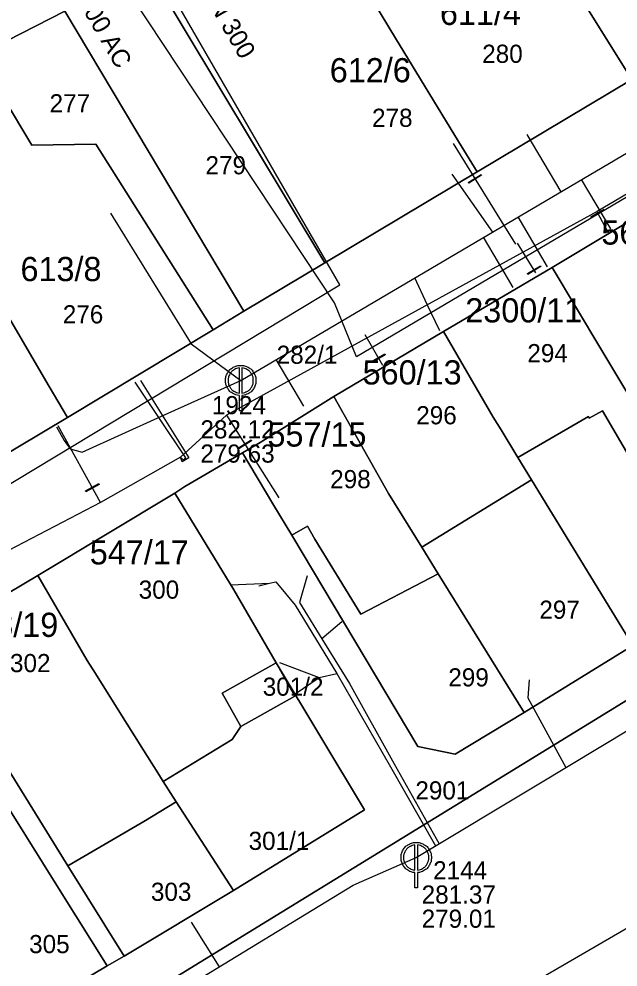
# Model space of a CAD drawing. Extents: x -571312 to -571060, y -1087128 to -1086933.
# Drawn here: x -571203.4 to -571153.9, y -1087085.5 to -1087007.2 of the extents above; entities that cross this region are included whole.
import ezdxf

# ---------------------------------------------------------------- set-up
doc = ezdxf.new("R2010")
doc.units = 0
for name, color, linetype in [('Adresní místo-text', 7, 'Continuous'), ('Armatura vodovodní', 7, 'Continuous'), ('Default', 7, 'Continuous'), ('Elektro NN - vedení', 7, 'Continuous'), ('Kanalizační přípojka', 7, 'Continuous'), ('Kanalizační stoka', 7, 'Continuous'), ('Kanalizační šachta', 7, 'Continuous'), ('Parcela-polygon', 7, 'Continuous'), ('Parcela-text', 7, 'Continuous'), ('Popis šachty', 7, 'Continuous'), ('Vodovodní přípojka', 7, 'Continuous'), ('Vodovodní řad', 7, 'Continuous'), ('Řad vodovodní popis', 7, 'Continuous')]:
    doc.layers.add(name, color=color, linetype=linetype)

msp = doc.modelspace()

# ---------------------------------------------------------------- linework, layer by layer
at = {"layer": 'Armatura vodovodní'}
for points in [[(-571165.211, -1087020.113), (-571166.272, -1087020.773), (-571166.314, -1087020.707), (-571165.252, -1087020.047), (-571165.211, -1087020.113)], [(-571155.048, -1087022.996), (-571156.133, -1087023.617), (-571156.172, -1087023.55), (-571155.087, -1087022.928), (-571155.048, -1087022.996)], [(-571160.313, -1087027.663), (-571161.379, -1087028.317), (-571161.42, -1087028.25), (-571160.354, -1087027.596), (-571160.313, -1087027.663)], [(-571173.176, -1087034.954), (-571174.256, -1087035.583), (-571174.295, -1087035.516), (-571173.215, -1087034.887), (-571173.176, -1087034.954)], [(-571184.208, -1087042.055), (-571185.264, -1087042.723), (-571185.306, -1087042.656), (-571184.25, -1087041.989), (-571184.208, -1087042.055)], [(-571196.804, -1087045.663), (-571197.895, -1087046.273), (-571197.933, -1087046.205), (-571196.842, -1087045.595), (-571196.804, -1087045.663)]]:
    msp.add_lwpolyline(points, dxfattribs=at)
at = {"layer": 'Default'}
for points in [[(-571185.213, -1087038.328), (-571185.471, -1087038.31), (-571185.733, -1087038.164), (-571186.03, -1087038), (-571186.195, -1087037.703), (-571186.36, -1087037.405), (-571186.36, -1087037.08), (-571186.36, -1087036.753), (-571186.192, -1087036.453), (-571186.023, -1087036.152), (-571185.725, -1087035.991), (-571185.427, -1087035.83), (-571185.11, -1087035.83), (-571184.795, -1087035.83), (-571184.496, -1087035.991), (-571184.197, -1087036.152), (-571184.028, -1087036.453), (-571183.86, -1087036.753), (-571183.86, -1087037.08), (-571183.86, -1087037.405), (-571184.025, -1087037.703), (-571184.19, -1087038), (-571184.487, -1087038.164), (-571184.749, -1087038.31), (-571185.007, -1087038.328)], [(-571185.213, -1087036.042), (-571185.41, -1087036.059), (-571185.625, -1087036.174), (-571185.874, -1087036.309), (-571186.013, -1087036.559), (-571186.152, -1087036.809), (-571186.152, -1087037.08), (-571186.152, -1087037.351), (-571186.016, -1087037.598), (-571185.879, -1087037.844), (-571185.63, -1087037.981), (-571185.418, -1087038.101), (-571185.213, -1087038.115)], [(-571185.007, -1087038.115), (-571184.802, -1087038.101), (-571184.588, -1087037.981), (-571184.341, -1087037.844), (-571184.204, -1087037.598), (-571184.068, -1087037.351), (-571184.068, -1087037.08), (-571184.068, -1087036.809), (-571184.208, -1087036.559), (-571184.348, -1087036.309), (-571184.597, -1087036.174), (-571184.81, -1087036.059), (-571185.007, -1087036.042)], [(-571170.713, -1087077.748), (-571170.971, -1087077.73), (-571171.233, -1087077.584), (-571171.53, -1087077.42), (-571171.695, -1087077.123), (-571171.86, -1087076.825), (-571171.86, -1087076.5), (-571171.86, -1087076.173), (-571171.692, -1087075.873), (-571171.523, -1087075.572), (-571171.225, -1087075.411), (-571170.927, -1087075.25), (-571170.61, -1087075.25), (-571170.295, -1087075.25), (-571169.996, -1087075.411), (-571169.697, -1087075.572), (-571169.528, -1087075.873), (-571169.36, -1087076.173), (-571169.36, -1087076.5), (-571169.36, -1087076.825), (-571169.525, -1087077.123), (-571169.69, -1087077.42), (-571169.987, -1087077.584), (-571170.249, -1087077.73), (-571170.507, -1087077.748)], [(-571170.713, -1087075.462), (-571170.91, -1087075.479), (-571171.125, -1087075.594), (-571171.374, -1087075.729), (-571171.513, -1087075.979), (-571171.652, -1087076.229), (-571171.652, -1087076.5), (-571171.652, -1087076.771), (-571171.516, -1087077.018), (-571171.379, -1087077.264), (-571171.13, -1087077.401), (-571170.918, -1087077.521), (-571170.713, -1087077.535)], [(-571170.507, -1087077.535), (-571170.302, -1087077.521), (-571170.088, -1087077.401), (-571169.841, -1087077.264), (-571169.704, -1087077.018), (-571169.568, -1087076.771), (-571169.568, -1087076.5), (-571169.568, -1087076.229), (-571169.708, -1087075.979), (-571169.848, -1087075.729), (-571170.097, -1087075.594), (-571170.31, -1087075.479), (-571170.507, -1087075.462)]]:
    msp.add_open_spline(points, degree=3, dxfattribs=at)
at = {"layer": 'Elektro NN - vedení'}
msp.add_lwpolyline([(-571071.926, -1087014.396), (-571073.5, -1087015.707), (-571083.992, -1087003.116), (-571092.911, -1086996.034), (-571095.272, -1086994.46), (-571113.896, -1086998.657), (-571175.538, -1087035.118), (-571177.374, -1087030.659), (-571213.311, -1086976.361), (-571216.983, -1086969.541), (-571228.263, -1086944.884), (-571229.263, -1086941.883)], dxfattribs=at)
at = {"layer": 'Kanalizační přípojka'}
for points in [[(-571161.465, -1087016.747), (-571160.068, -1087019.116), (-571158.671, -1087021.484)], [(-571167.678, -1087020.016), (-571165.996, -1087022.414), (-571164.314, -1087024.813)], [(-571154.546, -1087024.54), (-571155.747, -1087022.504), (-571156.948, -1087020.468)], [(-571195.864, -1087023.248), (-571192.527, -1087028.649), (-571189.19, -1087034.05), (-571185.11, -1087037.08)], [(-571159.76, -1087027.688), (-571162.193, -1087023.562)], [(-571162.589, -1087029.399), (-571163.815, -1087027.32), (-571165.041, -1087025.242)], [(-571168.666, -1087032.982), (-571169.698, -1087030.789), (-571170.729, -1087028.597)], [(-571179.904, -1087039.214), (-571182.182, -1087035.353)], [(-571200.32, -1087040.9), (-571199.69, -1087042.04), (-571199.2, -1087042.73), (-571198.22, -1087042.99), (-571191.665, -1087040.035), (-571185.11, -1087037.08)], [(-571179.61, -1087053.22), (-571180.251, -1087055.413), (-571178.191, -1087058.772), (-571176.13, -1087062.13), (-571172.424, -1087068.745), (-571168.717, -1087075.359)], [(-571185.918, -1087053.96), (-571182.733, -1087053.834)], [(-571183.62, -1087054.04), (-571182.73, -1087053.83), (-571182.2, -1087053.71), (-571180.617, -1087055.636), (-571177.161, -1087061.302), (-571172.74, -1087068.996), (-571169.02, -1087075.542)], [(-571176.744, -1087057.029), (-571178.403, -1087058.424)], [(-571181.91, -1087060.396), (-571178.635, -1087061.611)], [(-571180.61, -1087062.978), (-571178.635, -1087061.611), (-571177.161, -1087061.302)], [(-571161.29, -1087061.81), (-571161.39, -1087063.31), (-571158.241, -1087069.047)], [(-571189.19, -1087081.84), (-571186.894, -1087085.536)]]:
    msp.add_lwpolyline(points, dxfattribs=at)
at = {"layer": 'Kanalizační stoka'}
for points in [[(-571185.11, -1087037.08), (-571141.1, -1087011.12)], [(-571170.61, -1087076.5), (-571160.495, -1087070.405), (-571150.38, -1087064.31)], [(-571228.76, -1087111.04), (-571202.29, -1087094.915), (-571175.82, -1087078.79), (-571170.61, -1087076.5)]]:
    msp.add_lwpolyline(points, dxfattribs=at)
at = {"layer": 'Kanalizační šachta'}
for points in [[(-571185.213, -1087038.115), (-571185.213, -1087036.042)], [(-571185.007, -1087036.042), (-571185.007, -1087038.115)], [(-571185.007, -1087038.328), (-571185.007, -1087039.58), (-571185.213, -1087039.58), (-571185.213, -1087038.328)], [(-571170.713, -1087077.535), (-571170.713, -1087075.462)], [(-571170.507, -1087075.462), (-571170.507, -1087077.535)], [(-571170.507, -1087077.748), (-571170.507, -1087079), (-571170.713, -1087079), (-571170.713, -1087077.748)]]:
    msp.add_lwpolyline(points, dxfattribs=at)
at = {"layer": 'Parcela-polygon'}
for points in [[(-571144.15, -1087007.02), (-571155.86, -1086984.54), (-571166.67, -1086989.97), (-571152.8, -1087012.2)], [(-571208.98, -1086985.45), (-571218.36, -1086988.9), (-571217.04, -1086992.42), (-571226.94, -1086996.1), (-571217.97, -1087015.93), (-571206.82, -1087010.23), (-571199.65, -1087006.57), (-571207.52, -1086988.77)], [(-571179.74, -1086996.54), (-571179.19, -1086997.45), (-571175.25, -1087003.94), (-571172.31, -1087008.78), (-571167.11, -1087017.33), (-571165.57, -1087019.85), (-571152.8, -1087012.2), (-571166.67, -1086989.97)], [(-571179.19, -1086997.45), (-571179.74, -1086996.54), (-571192.72, -1087003.08), (-571178.15, -1087027.35), (-571165.57, -1087019.85), (-571167.11, -1087017.33), (-571172.31, -1087008.78), (-571175.25, -1087003.94)], [(-571178.15, -1087027.35), (-571192.72, -1087003.08), (-571199.65, -1087006.57), (-571184.85, -1087031.35)], [(-571184.85, -1087031.35), (-571199.65, -1087006.57), (-571206.82, -1087010.23), (-571202.38, -1087017.63), (-571197.08, -1087017.54), (-571187.38, -1087032.88)], [(-571197.08, -1087017.54), (-571202.38, -1087017.63), (-571206.82, -1087010.23), (-571217.97, -1087015.93), (-571215.05, -1087019.09), (-571210.21, -1087024.35), (-571206.07, -1087028.84), (-571200.94, -1087037.57), (-571199.42, -1087040.15), (-571187.38, -1087032.88)], [(-571210.21, -1087024.35), (-571215.05, -1087019.09), (-571217.97, -1087015.93), (-571222.72, -1087018.32), (-571218.79, -1087022.67), (-571223.54, -1087027.82), (-571216.62, -1087040.62), (-571216.21, -1087040.39), (-571212.67, -1087046.57), (-571212.04, -1087047.66), (-571199.42, -1087040.15), (-571200.94, -1087037.57), (-571206.07, -1087028.84)], [(-571150.57, -1087022.45), (-571159.39, -1087027.73), (-571155.35, -1087034.47), (-571153.13, -1087038.18), (-571151.82, -1087040.36), (-571143.27, -1087035.13), (-571144.87, -1087032.36), (-571146.38, -1087029.72), (-571146.72, -1087029.14)], [(-571151.82, -1087040.36), (-571153.13, -1087038.18), (-571155.35, -1087034.47), (-571159.39, -1087027.73), (-571168.35, -1087033.04), (-571164.25, -1087040.1), (-571163.6, -1087041.16), (-571162.21, -1087043.44), (-571156.38, -1087040.06), (-571156.31, -1087040.18), (-571155.22, -1087039.59), (-571151.14, -1087046.55), (-571148.91, -1087045.23)], [(-571164.25, -1087040.1), (-571168.35, -1087033.04), (-571177.42, -1087038.4), (-571172.91, -1087046.42), (-571170.16, -1087050.86), (-571161.09, -1087045.28), (-571162.21, -1087043.44), (-571163.6, -1087041.16)], [(-571177.42, -1087038.4), (-571183.51, -1087042.2), (-571184.97, -1087043.06), (-571182.46, -1087047.26), (-571180.9, -1087049.87), (-571179.59, -1087049.13), (-571178.99, -1087050.2), (-571175.19, -1087056.39), (-571168.8, -1087053.05), (-571170.16, -1087050.86), (-571172.91, -1087046.42)], [(-571148.91, -1087045.23), (-571151.14, -1087046.55), (-571155.22, -1087039.59), (-571156.31, -1087040.18), (-571156.38, -1087040.06), (-571162.21, -1087043.44), (-571161.09, -1087045.28), (-571152.72, -1087058.97), (-571143.89, -1087053.63)], [(-571161.09, -1087045.28), (-571170.16, -1087050.86), (-571168.8, -1087053.05), (-571161.7, -1087064.52), (-571152.72, -1087058.97)], [(-571201.86, -1087053.18), (-571197.8, -1087060.21), (-571197.12, -1087061.3), (-571195.24, -1087064.3), (-571193.15, -1087067.62), (-571191.96, -1087069.51), (-571191.52, -1087070.21), (-571185.82, -1087066.75), (-571185.11, -1087065.67), (-571186.65, -1087062.93), (-571182.17, -1087060.4), (-571185.69, -1087054.37), (-571190.56, -1087046.39)], [(-571161.7, -1087064.52), (-571168.8, -1087053.05), (-571175.19, -1087056.39), (-571178.99, -1087050.2), (-571179.59, -1087049.13), (-571180.9, -1087049.87), (-571170.47, -1087067.33), (-571167.4, -1087067.96)], [(-571210.82, -1087058.52), (-571206.5, -1087065.72), (-571199.38, -1087077.18), (-571193.1, -1087073.51), (-571190.45, -1087071.91), (-571191.52, -1087070.21), (-571191.96, -1087069.51), (-571193.15, -1087067.62), (-571195.24, -1087064.3), (-571197.12, -1087061.3), (-571197.8, -1087060.21), (-571201.86, -1087053.18)], [(-571219.73, -1087063.8), (-571215.85, -1087070.21), (-571214.37, -1087072.67), (-571213.37, -1087074.33), (-571210.64, -1087078.7), (-571208.46, -1087077.42), (-571209.1, -1087076.39), (-571205.73, -1087074.32), (-571206.54, -1087072.99), (-571204.26, -1087072.46), (-571200.02, -1087079.25), (-571196.13, -1087085.46), (-571194.74, -1087084.64), (-571199.38, -1087077.18), (-571206.5, -1087065.72), (-571210.82, -1087058.52)], [(-571182.17, -1087060.4), (-571180.64, -1087063.16), (-571185.11, -1087065.67), (-571185.82, -1087066.75), (-571191.52, -1087070.21), (-571190.45, -1087071.91), (-571185.7, -1087079.22), (-571174.89, -1087072.57)], [(-571182.17, -1087060.4), (-571186.65, -1087062.93), (-571185.11, -1087065.67), (-571180.64, -1087063.16)], [(-571199.38, -1087077.18), (-571194.74, -1087084.64), (-571185.7, -1087079.22), (-571190.45, -1087071.91), (-571193.1, -1087073.51)], [(-571205.73, -1087074.32), (-571209.1, -1087076.39), (-571208.46, -1087077.42), (-571210.64, -1087078.7), (-571210.13, -1087079.52), (-571203.69, -1087089.94), (-571196.13, -1087085.46), (-571200.02, -1087079.25), (-571204.26, -1087072.46), (-571206.54, -1087072.99)]]:
    msp.add_lwpolyline(points, close=True, dxfattribs=at)
for points in [[(-571152.8, -1087012.2), (-571165.57, -1087019.85), (-571178.15, -1087027.35), (-571184.85, -1087031.35), (-571187.38, -1087032.88), (-571199.42, -1087040.15), (-571212.04, -1087047.66), (-571212.62, -1087048.01), (-571217.5, -1087050.91), (-571220.52, -1087052.71), (-571223.27, -1087054.35), (-571244.48, -1087067.05), (-571249.13, -1087069.82), (-571252.04, -1087071.56), (-571254.73, -1087073.17), (-571257.35, -1087074.74), (-571258.59, -1087075.48), (-571259.95, -1087076.45), (-571260.789, -1087077.05)], [(-571238.048, -1087115.573), (-571084.13, -1087021.07)], [(-571100.979, -1087051.983), (-571102.73, -1087043.67), (-571081.09, -1087028.01), (-571079.74, -1087027.03), (-571084.13, -1087021.07), (-571238.048, -1087115.573)], [(-571254.973, -1087086.903), (-571253.39, -1087085.95), (-571254.21, -1087084.57), (-571245.94, -1087079.58), (-571237.74, -1087074.6), (-571228.73, -1087069.23), (-571219.73, -1087063.8), (-571210.82, -1087058.52), (-571201.86, -1087053.18), (-571190.56, -1087046.39), (-571189.72, -1087045.85), (-571184.97, -1087043.06), (-571183.51, -1087042.2), (-571177.42, -1087038.4), (-571168.35, -1087033.04), (-571159.39, -1087027.73), (-571150.57, -1087022.45)], [(-571152.72, -1087058.97), (-571161.7, -1087064.52), (-571167.4, -1087067.96), (-571170.47, -1087067.33), (-571180.9, -1087049.87), (-571182.46, -1087047.26), (-571184.97, -1087043.06), (-571189.72, -1087045.85), (-571190.56, -1087046.39), (-571185.69, -1087054.37), (-571182.17, -1087060.4), (-571174.89, -1087072.57), (-571185.7, -1087079.22), (-571194.74, -1087084.64), (-571196.13, -1087085.46), (-571203.69, -1087089.94), (-571212.71, -1087095.11), (-571213.81, -1087095.76), (-571221.44, -1087100.23), (-571229.69, -1087105.23), (-571235.88, -1087109.23), (-571239.44, -1087111.53), (-571240.174, -1087111.972)], [(-571238.048, -1087115.573), (-571230.994, -1087127.523), (-571100.979, -1087051.983)]]:
    msp.add_lwpolyline(points, dxfattribs=at)
at = {"layer": 'Vodovodní přípojka'}
for p, q in [((-571167.571, -1087017.498), (-571163.592, -1087023.902)), ((-571163.592, -1087023.902), (-571162.408, -1087025.807)), ((-571160.725, -1087028.186), (-571162.236, -1087025.725)), ((-571174.867, -1087033.292), (-571173.397, -1087035.816)), ((-571186.289, -1087039.932), (-571181.967, -1087046.77))]:
    msp.add_line(p, q, dxfattribs=at)
for points in [[(-571155.687, -1087023.126), (-571155.61, -1087023.273), (-571154.739, -1087024.918)], [(-571193.395, -1087037.086), (-571189.384, -1087043.478), (-571189.936, -1087043.803), (-571190.097, -1087043.426)], [(-571190.097, -1087043.426), (-571189.869, -1087043.631), (-571189.642, -1087043.483), (-571193.834, -1087037.222)], [(-571196.691, -1087047.158), (-571200.198, -1087040.83)]]:
    msp.add_lwpolyline(points, dxfattribs=at)
at = {"layer": 'Vodovodní řad'}
for points in [[(-571259.706, -1087078.885), (-571257.725, -1087077.417), (-571211.542, -1087050.048), (-571176.933, -1087029.184), (-571227.483, -1086941.667)], [(-571118.52, -1087001.2), (-571121.219, -1087002.471), (-571130.326, -1087008.201), (-571146.537, -1087017.741), (-571155.651, -1087023.106), (-571186.289, -1087039.932), (-571190.097, -1087043.426), (-571196.691, -1087047.158), (-571208.123, -1087053.111), (-571216.72, -1087058.494), (-571222.809, -1087062.06), (-571226.167, -1087064.027), (-571239.701, -1087072.13)]]:
    msp.add_lwpolyline(points, dxfattribs=at)

# ---------------------------------------------------------------- texts
at = {"layer": 'Adresní místo-text'}
for s, p in [('611/4', (-571168.655, -1087007.7)), ('612/6', (-571177.755, -1087012.44)), ('562/9', (-571155.315, -1087025.85)), ('613/8', (-571203.305, -1087028.87)), ('2300/11', (-571166.558, -1087032.28)), ('560/13', (-571175.041, -1087037.41)), ('557/15', (-571182.901, -1087042.54)), ('547/17', (-571197.581, -1087052.28)), ('548/19', (-571208.361, -1087058.27))]:
    msp.add_text(s, height=2, dxfattribs=at).set_placement(p)
at = {"layer": 'Parcela-text'}
for s, p in [('280', (-571165.16, -1087010.83)), ('277', (-571200.9, -1087014.92)), ('278', (-571174.26, -1087016.12)), ('279', (-571188.02, -1087020.04)), ('276', (-571199.81, -1087032.36)), ('282/1', (-571182.14, -1087035.7)), ('294', (-571161.43, -1087035.57)), ('296', (-571170.61, -1087040.7)), ('298', (-571177.72, -1087045.98)), ('300', (-571193.54, -1087055.11)), ('297', (-571160.44, -1087056.77)), ('302', (-571204.17, -1087061.18)), ('299', (-571167.96, -1087062.36)), ('301/2', (-571183.29, -1087063.13)), ('2901', (-571170.68, -1087071.7)), ('301/1', (-571184.46, -1087075.87)), ('303', (-571192.53, -1087080.08)), ('305', (-571202.59, -1087084.4))]:
    msp.add_text(s, height=1.5, dxfattribs=at).set_placement(p)
at = {"layer": 'Popis šachty'}
for s, p in [('1924', (-571187.492, -1087039.867)), ('282.12', (-571188.442, -1087041.867)), ('279.63', (-571188.442, -1087043.867)), ('2144', (-571169.214, -1087078.305)), ('281.37', (-571170.163, -1087080.305)), ('279.01', (-571170.163, -1087082.305))]:
    msp.add_text(s, height=1.5, dxfattribs=at).set_placement(p)
at = {"layer": 'Řad vodovodní popis'}
for s, p in [('AC DN 300', (-571190.179, -1087001.848)), ('DN 300 AC', (-571200.4, -1087002.629))]:
    msp.add_text(s, height=1.5, rotation=300.01101, dxfattribs=at).set_placement(p)

doc.saveas('drawing.dxf')
